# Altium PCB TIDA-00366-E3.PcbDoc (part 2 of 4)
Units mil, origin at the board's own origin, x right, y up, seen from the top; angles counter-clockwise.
Board outline 6298.95 x 6141.73 mil, 4 copper layers (Top Layer, GND, PWR, Bottom Layer), stack 79.834 mil thick; 362 components, 168 nets, 919 pads, 271 vias.
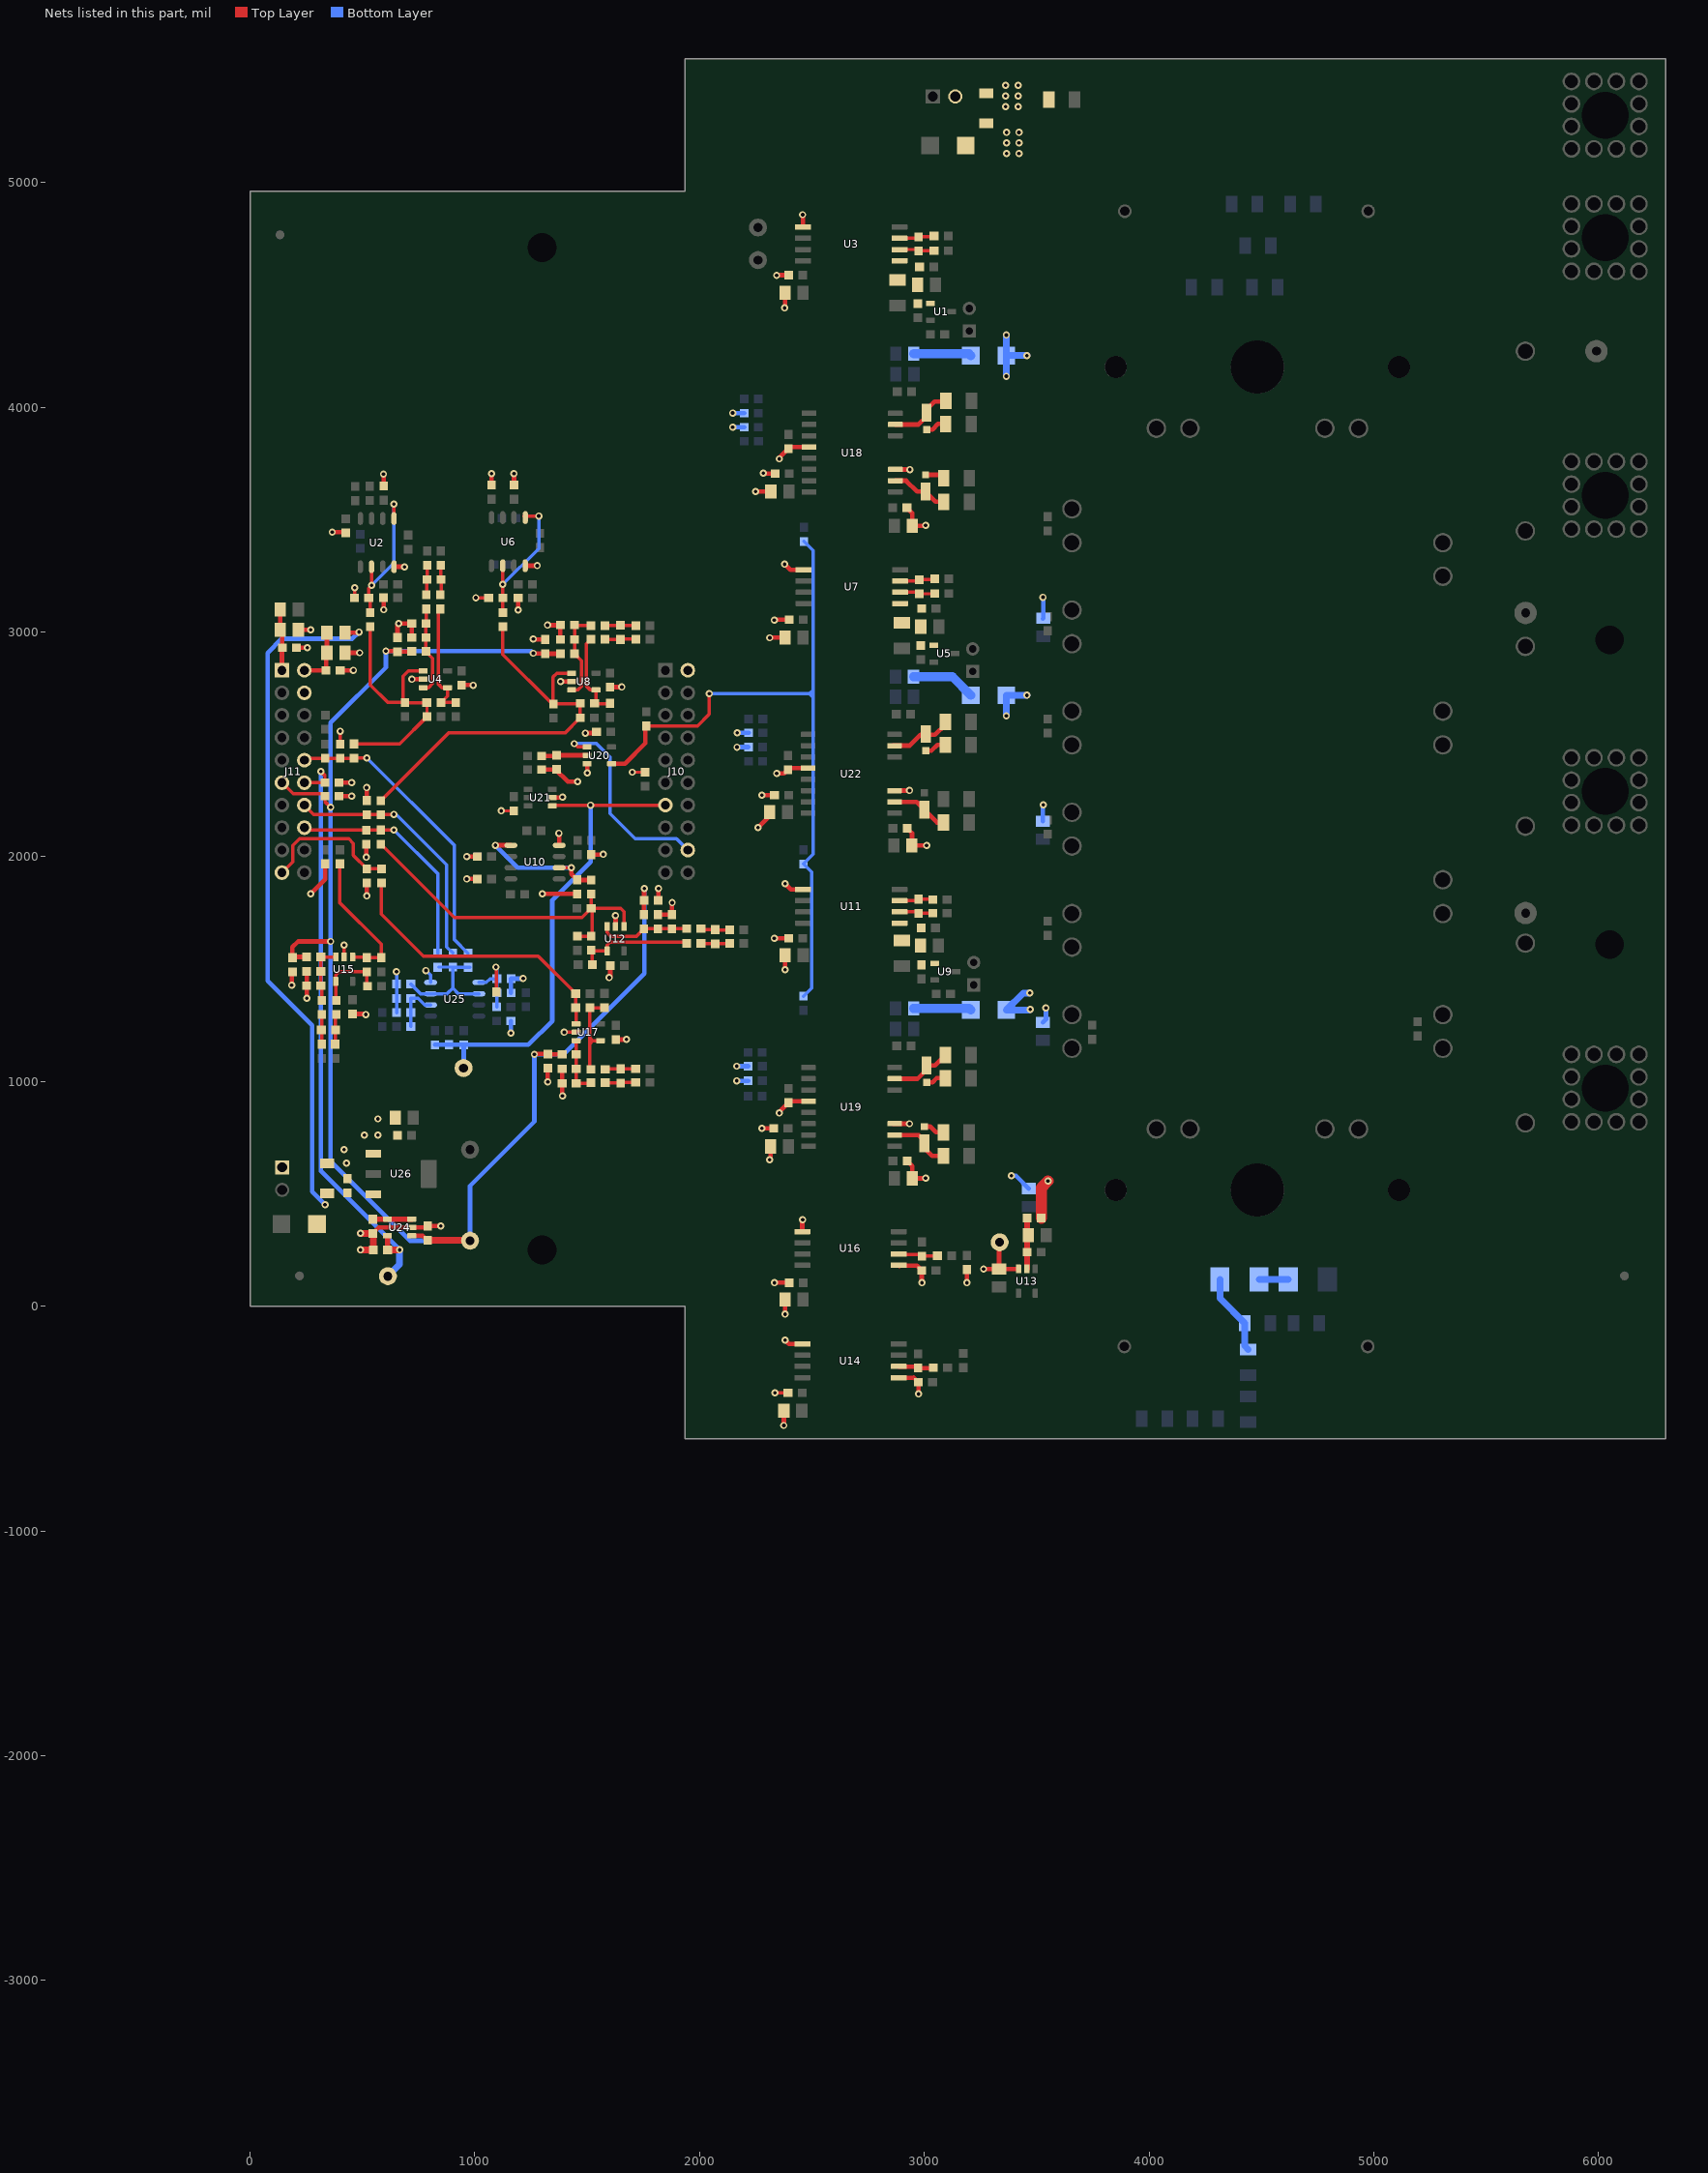
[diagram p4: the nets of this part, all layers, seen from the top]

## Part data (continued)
C3 C11 C13 C17 C25 C27 C31 C39 C41: library part CMP-0007191-4, "CAP, CERM, 180 pF, 50 V, +/- 5%, C0G/NP0, 0603", Cap_Case=0603, Manufacturer=MuRata, Supplier Part Number 1=490-1433-1-ND, TempCo=C0G/NP0, Tolerance_%=5%, Value1=Unknown, Value2=50V, ValueDisplayed=180pF
C4 C6 C18 C20 C32 C34 C43 C45 C48 C59 C69 C70 C72 C73 C79 C81 C83 C84 C87 C92 C94: "CAP, CERM, 4.7 µF, 50 V, +/- 10%, X5R, 0805", Cap_Case=0805, Manufacturer=TDK, Supplier Part Number 1=445-5980-1-ND, TempCo=X5R, Tolerance_%=10, Value1=Unknown, Value2=50V, ValueDisplayed=4.7µF
C5 C7 C9 C14 C19 C21 C23 C28 C33 C35 C37 C42 C44 C47 C49 C50 C53 C56 C58 C60 C61 C64 C66 C74 C75 C76 C77 C78 C80 C85 C86 C93 C97 C98 C104 C105 C109 C110 C111 C112: library part CMP-0007144-4, "CAP, CERM, 0.1 uF, 50 V, +/- 10%, X7R, 0603", Cap_Case=0603, Manufacturer=MuRata, Supplier Part Number 1=490-4779-1-ND, TempCo=X7R, Tolerance_%=10%, Value1="0.02 ohm", Value2=50V, ValueDisplayed=0.1uF
C8 C22 C36: "CAP, CERM, 1500 pF, 100 V, +/- 5%, X7R, 0603", Cap_Case=0603, Manufacturer=AVX, Supplier Part Number 1=478-3703-1-ND, TempCo=X7R, Tolerance_%=5, Value1="0.229 ohm", Value2=100V, ValueDisplayed=1500pF
C10 C12 C24 C26 C38 C40 C46 C51 C52 C54 C57 C62 C63 C65 C71: "CAP, CERM, 0.01 µF, 16 V, +/- 10%, X7R, 0603", Cap_Case=0603, Manufacturer="Wurth Elektronik", Supplier Part Number 1=732-7959-1-ND, TempCo=X7R, Tolerance_%=10, Value1=Unknown, Value2=16V, ValueDisplayed=0.01µF
C67 C68 C82: library part CMP-0007050-4, "CAP, CERM, 0.47 uF, 50 V, +/- 10%, X7R, 0603", Cap_Case=0603, Manufacturer=TDK, Supplier Part Number 1=445-5952-1-ND, TempCo=X7R, Tolerance_%=10%, Value1="0.010974 ohm", Value2=50V, ValueDisplayed=0.47uF
C88 C106: library part CMP-0009015-2, "CAP, CERM, 10 uF, 50 V, +/- 10%, X5R, AEC-Q200 Grade 1, 1206", Cap_Case=1206, Manufacturer=MuRata, Supplier Part Number 1=490-12456-1-ND, TempCo=X5R, Tolerance_%=10%, Value1=Unknown, Value2=50V, ValueDisplayed=10uF
C89 C90: library part CMP-0012358-3, "CAP, Film, 5 uF, 1300 V, +/- 10%, 0.0098 ohm, TH", Cap_Case=31.5x22x36.5mm, Manufacturer=TDK, Supplier Part Number 1=495-3930-ND, Tolerance_%=10%, Value1="0.0098 ohm", Value2=1300V, ValueDisplayed=5uF
C91 C96 C99 C100 C101 C102: library part CMP-0078152-1, "CAP, CERM, 10 pF, 100 V,+/- 5%, C0G/NP0, 0603", Cap_Case=0603, Manufacturer="Wurth Elektronik", Supplier Part Number 1=732-12038-1-ND, TempCo=C0G/NP0, Tolerance_%=5%, Value2=100V, ValueDisplayed=10pF
C95: "CAP, CERM, 0.1 µF, 50 V, +/- 10%, X7R, 0603", Cap_Case=0603, Manufacturer=TDK, Supplier Part Number 1=445-1314-1-ND, TempCo=X7R, Tolerance_%=10, Value1="0.017 ohm", Value2=50V, ValueDisplayed=0.1µF
C103 C107 C113: library part CMP-0006972-5, "CAP, CERM, 820 pF, 50 V, +/- 10%, X7R, 0603", Cap_Case=0603, Manufacturer=Kemet, Supplier Part Number 1=399-1078-1-ND, TempCo=X7R, Tolerance_%=10%, Value1=Unknown, Value2=50V, ValueDisplayed=820pF
C108: library part CMP-0007990-2, "CAP, CERM, 22 uF, 25 V, +/- 20%, X5R, 0805", Cap_Case=0805, Manufacturer="Samsung Electro-Mechanics", Supplier Part Number 1=1276-2908-1-ND, TempCo=X5R, Tolerance_%=20%, Value1=Unknown, Value2=25V, ValueDisplayed=22uF
Caution1: library part IEC_Caution, "IEC 61010-1 Caution Warning"
"CAUTION HOT SURFACE1": library part IEC_HotSurface, "IEC 61010-1 Hot Surface Warning"
D1 D2: "Diode, Zener, 200 V, 550 mW, SMB", Manufacturer="ON Semiconductor", Power_W=0.55, Supplier Part Number 1=863-1SMB5956BT3G, Value1=0.55W
D3 D4 D9: "Diode, Ultrafast, 1300 V, 1 A, SMA", Manufacturer=Vishay-Semiconductor, Supplier Part Number 1=BYG23T-M3/CT-ND, Value1=1A, Value2=1.9V
D5 D6 D7 D8 D10 D11: library part MSS1P3L-M3/89A, "Diode, Schottky, 30 V, 2 A, AEC-Q101, MicroSMP", Manufacturer=Vishay-Semiconductor, Supplier Part Number 1=MSS2P3-M3/89AGICT-ND, Value1=2A, Value2=0.6V
D12 D13: "Diode, Schottky, 100 V, 1 A, SMA", Manufacturer="Diodes Inc.", Supplier Part Number 1=B1100-FDICT-ND, Value1=1A, Value2=0.79V
FID1 FID2 FID3 FID4 FID5 FID6: "Fiducial mark.  There is nothing to buy or mount.", Manufacturer=N/A
H1 H2 H3 H4: library part "MH 3_0.5MM", "Mountin hole, NPTH Drill 3.2mm", Manufacturer=N/A
H5 H6 H7 H8: library part CMP-0003610-1, Manufacturer=Keystone, Supplier Part Number 1=36-1902C-ND
J1 J2 J3: "Header, 100mil, 2x1, TH", Manufacturer=Mill-Max, Supplier Part Number 1=ED7202-ND
J4 J5 J6 J7 J9: "Power Element Bush, M4, 12, TH", Manufacturer="Wurth Elektronik", Supplier Part Number 1=732-3207-ND
J8 J12: "Terminal Block, 2x1, 2.54mm, TH", Manufacturer="TE Connectivity", Supplier Part Number 1=A98333-ND
J10 J11: "Header, 100mil, 10x2, Gold, TH", Color=Black, Current_A=6.3, Manufacturer=Samtec, Supplier Part Number 1=SAM1028-10-ND, Voltage_V=550
LBL1: library part THT-14-423-10, "Thermal Transfer Printable Labels, 0.650\" W x 0.200\" H - 10,000 per roll", Alternate Manufacturer=-, Manufacturer=Brady, Supplier Part Number 1=2065596
LOGO1 LOGO4 LOGO5 LOGO6: library part IEC_HighVoltage, "IEC 61010-1 High Voltage Warning"
Logo2: library part Pb-Free
Logo3: library part FCC_disclaimer, "FCC_disclaimer"
Pb_Free1: library part ESD_Susceptible, "ESD Susceptible Symbol"
R1 R2 R6 R23 R27 R44 R48 R103 R106 R107 R116 R117 R125 R131 R151 R157: library part CMP-0025886-5, "RES, 10 k, 5%, 0.1 W, 0603", Manufacturer=Yageo, Power_W=100mW, Supplier Part Number 1=311-10KGRCT-ND, TempCo="100 ppm/C", Tolerance_%=5%, Value2=0.1W, Value_Code=10k0, ValueDisplayed=10k
R3 R7 R10 R14 R17 R20 R24 R28 R31 R35 R38 R41 R45 R49 R52 R56 R59 R62 R67 R71 R87 R102 R110 R111 R127: library part CMP-0025885-5, "RES, 0, 5%, 0.1 W, 0603", Manufacturer=Yageo, Power_W=100mW, Supplier Part Number 1=311-0.0GRCT-ND, TempCo="200 ppm/C", Tolerance_%=5%, Value2=0.1W, Value_Code=0000, ValueDisplayed=0
R4 R19 R25 R40 R46 R61: "RES, 100, 0.1%, 0.1 W, AEC-Q200 Grade 0, 0603", Manufacturer=Panasonic, Power_W=0.1, Supplier Part Number 1=P100DBCT-ND, TempCo="25 ppm/C", Value1=0.1%, Value2=0.1W, Value_Code=100R, ValueDisplayed=100
R5 R26 R47 R78 R92 R143 R145 R150 R152 R153 R156: library part CMP-0022736-4, "RES, 100, 1%, 0.1 W, 0603", Manufacturer=Yageo, Power_W=100mW, Supplier Part Number 1=311-100HRCT-ND, TempCo="100 ppm/C", Tolerance_%=1%, Value2=0.1W, Value_Code=100R, ValueDisplayed=100
R8 R21 R22 R29 R42 R43 R50 R63 R64 R86 R99: "RES, 7.50 k, 1%, 0.1 W, 0603", Manufacturer=Panasonic, Power_W=0.1, Supplier Part Number 1=P7.50KHCT-ND, TempCo="100 ppm/C", Tolerance_%=1, Value1=1%, Value2=0.1W, Value_Code=7k50, ValueDisplayed=7.50k
R9 R30 R51: library part CMP-0018732-3, "RES, 820, 5%, 0.25 W, AEC-Q200 Grade 0, 1206", Manufacturer=Vishay-Dale, Power_W=250mW, Supplier Part Number 1=541-820ECT-ND, TempCo="200 ppm/C", Tolerance_%=5%, Value2=0.25W, Value_Code=820R, ValueDisplayed=820
R11 R32 R53: "RES, 10.7 k, 0.1%, 0.1 W, 0603", Manufacturer="Susumu Co Ltd", Power_W=0.1, Supplier Part Number 1=RG16P10.7KBCT-ND, TempCo="25 ppm/C", Value1=0.1%, Value2=0.1W, Value_Code=10k7, ValueDisplayed=10.7k
R12 R13 R15 R16 R33 R34 R36 R37 R54 R55 R57 R58 R75 R76 R80 R81 R90 R91 R93 R94: "RES, 4.70 k, 1%, 0.1 W, 0603", Manufacturer="Yageo America", Power_W=0.1, Supplier Part Number 1=311-4.70KHRCT-ND, TempCo="200 ppm/C", Tolerance_%=1, Value1=1%, Value2=0.1W, Value_Code=4k70, ValueDisplayed=4.70k
R18 R39 R60 R77 R148 R149: "RES, 0, 5%, 0.1 W, 0603", Manufacturer=Vishay-Dale, Power_W=0.1, Supplier Part Number 1=541-0.0GCT-ND, TempCo="200 ppm/C", Tolerance_%=5, Value1=5%, Value2=0.1W, Value_Code=0000, ValueDisplayed=0
R65 R66 R69 R70 R73: library part CMP-0018060-2, "RES, 200 k, 1%, 0.25 W, 1206", Manufacturer="Yageo America", Power_W=250mW, Supplier Part Number 1=311-200KFRCT-ND, TempCo="100 ppm/C", Tolerance_%=1%, Value2=0.25W, Value_Code=200k
R68: library part CMP-0018756-2, "RES, 0, 5%, 0.25 W, 1206", Manufacturer=Rohm, Power_W=250mW, Supplier Part Number 1=RHM0.0ECT-ND, TempCo="200 ppm/C", Tolerance_%=5%, Value2=0.25W, Value_Code=0000, ValueDisplayed=0
R72 R85 R88 R98: library part CMP-0022816-5, "RES, 15.0 k, 1%, 0.1 W, 0603", Manufacturer=Yageo, Power_W=100mW, Supplier Part Number 1=311-15.0KHRCT-ND, TempCo="100 ppm/C", Tolerance_%=1%, Value2=0.1W, Value_Code=15k0, ValueDisplayed=15.0k
R74 R89: "RES, 39, 5%, 0.1 W, 0603", Manufacturer=Vishay-Dale, Power_W=0.1, Supplier Part Number 1=541-39GCT-ND, TempCo="200 ppm/C", Tolerance_%=5, Value1=5%, Value2=0.1W, Value_Code=39R0, ValueDisplayed=39
R79: library part CMP-0022990-5, "RES, 2.49 k, 1%, 0.1 W, 0603", Manufacturer=Yageo, Power_W=100mW, Supplier Part Number 1=311-2.49KHRCT-ND, TempCo="100 ppm/C", Tolerance_%=1%, Value2=0.1W, Value_Code=2k49, ValueDisplayed=2.49k
R100 R101 R120: library part CMP-0021875-2, "RES, 1.33, 1%, 0.125 W, 0805", Manufacturer="Yageo America", Power_W=125mW, Supplier Part Number 1=311-1.33CRCT-ND, TempCo="200 ppm/C", Tolerance_%=1%, Value2=0.125W, Value_Code=1R33, ValueDisplayed=1.33
R104 R105 R114 R115 R122 R130 R141: library part CMP-0018748-1, "RES, 0, 5%, 0.25 W, 1206", Manufacturer=Panasonic, Power_W=250mW, Supplier Part Number 1=P0.0ECT-ND, TempCo="600 ppm/C", Tolerance_%=5%, Value2=0.25W, Value_Code=0000, ValueDisplayed=0
R108 R109 R118 R119 R126 R132: "RES, 16.5, 1%, 0.25 W, 1206", Manufacturer=Vishay-Dale, Power_W=0.25, Supplier Part Number 1=541-16.5FCT-ND, TempCo="100 ppm/C", Tolerance_%=1, Value1=1%, Value2=0.25W, Value_Code=16R5, ValueDisplayed=16.5
R112 R113 R128: library part CMP-0022906-5, "RES, 20.0 k, 1%, 0.1 W, 0603", Manufacturer=Yageo, Power_W=100mW, Supplier Part Number 1=311-20.0KHRCT-ND, TempCo="100 ppm/C", Tolerance_%=1%, Value2=0.1W, Value_Code=20k0, ValueDisplayed=20.0k
R121 R123 R124: "RES, 0.005, 1%, 5 W, 20.32x4.80mm", Manufacturer=Bourns, Power_W=5, Supplier Part Number 1=PWR4412-2SDR0050F-ND, TempCo="20 ppm/C", Tolerance_%=1, Value1=1%, Value2=5W, Value_Code=5L000, ValueDisplayed=0.005
R129: library part CMP-0022692-3, "RES, 22.0 k, 1%, 0.1 W, AEC-Q200 Grade 0, 0603", Manufacturer=Panasonic, Power_W=100mW, Supplier Part Number 1=P22.0KHCT-ND, TempCo="100 ppm/C", Tolerance_%=1%, Value2=0.1W, Value_Code=22k0, ValueDisplayed=22.0k
R133 R139 R140 R142 R144 R146: "RES, 0, 5%, 0.125 W, 0805", Manufacturer=Vishay-Dale, Power_W=0.125, Supplier Part Number 1=541-0.0ACT-ND, TempCo="200 ppm/C", Tolerance_%=5, Value1=5%, Value2=0.125W, Value_Code=0000, ValueDisplayed=0
R134 R135 R136 R137 R138: "RES, 100 k, 5%, 0.25 W, 1206", Manufacturer=Vishay-Dale, Power_W=0.25, Supplier Part Number 1=541-100KECT-ND, TempCo="200 ppm/C", Tolerance_%=5, Value1=5%, Value2=0.25W, Value_Code=100k
R147: "RES, 1.0 k, 5%, 0.1 W, 0603", Manufacturer="Yageo America", Power_W=0.1, Supplier Part Number 1=311-1.0KGRCT-ND, TempCo="100 ppm/C", Tolerance_%=5, Value1=5%, Value2=0.1W, Value_Code=1k00, ValueDisplayed=1.0k
R154: "RES, 200, 0.1%, 0.1 W, 0603", Manufacturer="Susumu Co Ltd", Power_W=0.1, Supplier Part Number 1=RG16P200BCT-ND, TempCo="25 ppm/C", Value1=0.1%, Value2=0.1W, Value_Code=200R, ValueDisplayed=200
R155: "RES, 12.0 k, 0.1%, 0.1 W, 0603", Manufacturer="Susumu Co Ltd", Power_W=0.1, Supplier Part Number 1=RG16P12.0KBCT-ND, TempCo="25 ppm/C", Value1=0.1%, Value2=0.1W, Value_Code=12k0, ValueDisplayed=12.0k
R158 R160 R161 R162 R166: "RES, 10.0 k, 0.1%, 0.0375 W, 0603", Manufacturer="Vishay Sfernice", Power_W=0.0375, Supplier Part Number 1=PHTB-10KCT-ND, TempCo="15 ppm/C", Tolerance_%=0.1, Value1=0.1%, Value2=0.0375W, Value_Code=10k0, ValueDisplayed=10.0k
R159 R164: "RES, 0, 5%, 0.1 W, 0603", Manufacturer="Yageo America", Power_W=0.1, Supplier Part Number 1=311-0.0GRCT-ND, TempCo="200 ppm/C", Tolerance_%=5, Value1=5%, Value2=0.1W, Value_Code=0000, ValueDisplayed=0
R163: "RES, 0, 5%, 0.1 W, 0603", Manufacturer=Panasonic, Power_W=0.1, Supplier Part Number 1=P0.0GCT-ND, TempCo="600 ppm/C", Tolerance_%=5, Value1=5%, Value2=0.1W, Value_Code=0000, ValueDisplayed=0
R165: "RES, 8.20 k, 0.1%, 0.1 W, 0603", Manufacturer="Susumu Co Ltd", Power_W=0.1, Supplier Part Number 1=RG16P8.2KBCT-ND, TempCo="25 ppm/C", Value1=0.1%, Value2=0.1W, Value_Code=8k20, ValueDisplayed=8.20k
R167: "RES, 5.11 M, 1%, 0.1 W, 0603", Manufacturer=Vishay-Dale, Power_W=0.1, Supplier Part Number 1=541-5.11MHCT-ND, TempCo="100 ppm/C", Tolerance_%=1, Value1=1%, Value2=0.1W, Value_Code=5M11, ValueDisplayed=5.11M
TP1 TP2 TP3 TP7 TP8 TP9 TP10: "Test Point, Miniature, Red, TH", Color=Red, Manufacturer=Keystone, Supplier Part Number 1=36-5000-ND
TP4 TP5 TP6: library part PAD_100mil-40milhole, "100mil pad, 40mil hole", Manufacturer=Any
U1 U5 U9: "Adjustable Precision Shunt Regulator, 34 ppm / degC, 100 mA, -40 to 125 degC, 3-pin SOT-23 (DBZ), Green (RoHS & no Sb/Br)", Alternate Manufacturer="Texas Instruments", Alternate PartNumber=Equivalent, Rating=Catalog, Supplier Part Number 1=296-26715-2-ND, Temp Coeff(Max)(ppm/ degree C)=92, Temp Coeff(Typ)(ppm/ degree C)=34
U2 U6 U10 U25: "LinCMOS Dual Differential Comparators, D0008A", Alternate Manufacturer="Texas Instruments", Alternate PartNumber=TLC372QD
U3 U7 U11: "200 kHz, Fully-Differential Isolation Amplifier, DWV0008A", Alternate Manufacturer="Texas Instruments", Alternate PartNumber=AMC1301DWV
U4 U8 U12 U15 U17: "Precision, 20 MHz, 0.9 pA Ib, RRIO, CMOS Operational Amplifier, 1.8 to 5.5 V, -40 to 125 degC, 5-pin SOT23 (DBV0005A), Green (RoHS & no Sb/Br)", Alternate Manufacturer="Texas Instruments", Alternate PartNumber=Equivalent, Supplier Part Number 1=296-29480-2-ND, Total Supply Voltage(Max)(+5V is 5, +/-5V is 10)=5.5, Total Supply Voltage(Min)(+5V is 5, +/-5V is 10)=1.8
U13: library part CMP-0035558-1, "Single Output LDO, 150 mA, Fixed 5 V Output, 2.5 to 24 V Input, with Ultra-Low IQ, 5-pin SOT-23 (DBV), -40 to 125 degC, Green (RoHS & no Sb/Br)", Manufacturer="Texas Instruments"
U14 U16: library part CMP-0013503-1, "Precision, 2-V Input, Reinforced Isolated Amplifier, DWV0008A (SOIC-8)", Alternate Manufacturer="Texas Instruments", Alternate PartNumber=AMC1311DWV
U18 U19 U22: library part CMP-0083996-1, "4-A, 6-A, 5.7-kVRMS Isolated Dual-Channel Gate Driver with Enable, DWK0014A (SOIC-14)", Alternate Manufacturer="Texas Instruments", Alternate PartNumber=UCC21530DWKR
U20: library part CMP-0051622-1, "Single 2-Input Positive-OR Gate, DBV0005A, LARGE T&R", F @ Nom Voltage(Max)(Mhz)=150, Generic Part Number=SN74LVC1G32, ICC @ Nom Voltage(Max)(mA)=0.01, Manufacturer="Texas Instruments", Operating Temperature Range(C)="-40 to 125,-40 to 85", Rating=Catalog, tpd @ Nom Voltage(Max)(ns)=7.2,4.4,3.6,3.4, Voltage(Nom)(V)=1.8,2.5,3.3,5
U21: library part CMP-0051219-1, "Single 3-Input Positive-AND Gate, DBV0006A, LARGE T&R", F @ Nom Voltage(Max)(Mhz)=150, Generic Part Number=SN74LVC1G11, ICC @ Nom Voltage(Max)(mA)=0.01, Manufacturer="Texas Instruments", Operating Temperature Range(C)="-40 to 125,-40 to 85", Rating=Catalog, tpd @ Nom Voltage(Max)(ns)=20,7.8,6.2,4.6, Voltage(Nom)(V)=1.8,2.5,3.3,5
U23: library part "MWI 50-12T7T", "IGBT MOD 1200V 85A E2-Pack", Manufacturer=IXYS, Supplier Part Number 1=747-MIXA60W1200TED
U24: "Low-Drift, Low-Power, Dual-Output, VREF and VREF / 2 Voltage References, DDC0005A", Alternate Manufacturer="Texas Instruments", Alternate PartNumber=REF2033AIDDCT
U26: "FIXED LOW-DROPOUT VOLTAGE REGULATOR, DCY0003A", Alternate Manufacturer="Texas Instruments"
ZZ1: library part AssemblyNoteLabel, Alternate Manufacturer=-
ZZ2 ZZ3 ZZ4: library part AssemblyNote, Alternate Manufacturer=-

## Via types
v1: diameter 32, hole 16, Top Layer to Bottom Layer, 271 vias

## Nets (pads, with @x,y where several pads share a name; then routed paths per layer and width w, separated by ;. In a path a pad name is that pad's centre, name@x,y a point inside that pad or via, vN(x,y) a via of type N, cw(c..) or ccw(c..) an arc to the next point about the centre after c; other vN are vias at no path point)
1V65_REF: C14.2 C28.2 C42.2 C56.2 C66.2 C97.1 C112.1 J11.11 R22.1 R43.1 R64.1 R86.1 R99.1 TP8.1 U24.1 | length 7075.5
  Top Layer w15: J11.11@141.73,2329.45 191.73,2279.45 323.24,2279.45 C97.1@333.24,2269.45 333.24,2244.95 v1(358.73,2219.45) ; C112.1@786.92,294.11 C112.1@790.38,294.11
  Top Layer w20: C56.2@188.73,1550.9 188.73,1597.91 213.73,1622.91 v1(358.73,1622.91) ; C56.2@192.23,1554.4 R86.1@252.23,1554.4 ; v1(604.23,2914.95) 654.73,2914.95 656.24,2913.45 R22.1@719.24,2913.45 ; U24.1@719.51,313.21 767.83,313.21 C112.1@786.92,294.11 ; v1(1260.07,2905.12) 1261.57,2903.63 C14.2@1313.06,2903.63 1313.57,2903.12 R43.1@1380.57,2903.12 ; v1(1264.73,1120.91) 1266.23,1122.4 C66.2@1324.73,1122.4 1326.23,1120.91 R99.1@1388.24,1120.91 ; R64.1@1752.41,1742.4 1752.41,1805.4 C42.2@1752.92,1805.91 1752.92,1857.4 v1(1754.41,1858.9)
  Top Layer w30: C112.1@790.38,294.11 976.07,294.11 TP8.1@978.73,291.45
  Bottom Layer w20: v1(1260.07,2905.12) 1250.24,2914.95 v1(604.23,2914.95) 604.23,2842.23 358.73,2596.73 v1(358.73,2219.45) v1(358.73,1622.91) 358.73,644.27 711.55,291.45 TP8.1@978.73,291.45 978.73,535.73 1264.73,821.73 v1(1264.73,1120.91) 1395.87,1120.91 1754.41,1479.45 v1(1754.41,1858.9)
3V3_REF: C98.1 C111.1 J11.12 TP7.1 U24.5 | length 2679.6
  Top Layer w15: J11.12@241.73,2329.45 C98.1@333.24,2329.45 333.24,2360.95 v1(314.73,2379.45)
  Top Layer w20: C111.1@611.24,251.24 C111.1@611.87,250.61
  Top Layer w23.62: C111.1@611.24,251.24 U24.5@611.24,313.21
  Top Layer w30: C111.1@611.87,250.61 v1(665.38,250.61)
  Bottom Layer w20: v1@315.73,2378.45 v1(314.73,2379.45) 314.73,601.25 v1(665.38,250.61)
  Bottom Layer w30: TP7.1@613.38,133.61 665.38,185.61 v1(665.38,250.61)
5V0: C104.1 C105.1 C106.1 D13.1 R144.2 U24.3 U24.4 U26.3 | length 3244.3
  Top Layer w20: R144.2@421.73,2996.45 481.73,2996.45 v1(484.73,2999.45)
  Top Layer w23.62: C105.1@546.38,387.1 547.28,388.01 U24.4@611.24,388.01 U24.3@719.51,388.01
  Bottom Layer w20: v1(333.73,451.45) 276,509.18 276,1249 78,1447 78,2907 141,2970 455.28,2970 v1(484.73,2999.45)
5V_VDC: C45.1 C47.2 C58.2 R129.1 TP3.1 U13.3 U14.1 U16.1 | length 647.2
  Top Layer w20: U14.1@2886.13,-318 2952.14,-318 2952.42,-317.73 C47.2@2973.24,-338.55 2973.73,-339.05 v1(2973.73,-390.55) ; U16.1@2889.3,179.45 2890.12,180.27 2967.42,180.27 C58.2@2988.24,159.45 2988.24,105.95 v1(2989.73,104.45) ; v1(3189.73,104.45) R129.1@3189.73,162.95 ; v1(3263.33,165.32) C45.1@3332.33,165.32 ; TP3.1@3334.73,284.45 3332.33,282.05 C45.1@3332.33,165.32 ; U13.3@3419.93,164.45 3418.6,164.45 3417.73,165.32 C45.1@3332.33,165.32
+16V_GPS: C72.2 C73.2 C75.2 C76.2 C84.2 C85.2 C88.1 D3.2 D4.2 D9.2 D12.1 R67.1 U18.11 U19.11 U22.11 | length 1542.3
  Top Layer w20: U19.11@2860.12,811.86 v1(2934.13,811.86) ; U18.11@2861,3722.45 v1(2935,3722.45) ; U22.11@2866.86,2294 2933.55,2294 v1(2934,2294.45) ; C75.2@2922.23,3552.45 2945.73,3528.95 C72.2@2945.73,3472.45 3003.73,3472.45 v1(3005.73,3474.45) ; C85.2@2923.23,2126.45 2944.73,2104.95 C84.2@2944.73,2049.45 v1(3009.73,2049.45) ; C76.2@2923.36,645.86 2945.86,623.36 C73.2@2945.86,568.86 3004.15,568.86 v1(3005.73,570.45)
  Top Layer w50: R67.1@3519.83,392.32 3519.83,527.54 v1(3549.73,557.45)
  Bottom Layer w30: v1(3364.47,2626.71) D9.2@3364.47,2718.45 v1(3456.21,2718.45) ; v1(3364.47,4137.71) D3.2@3364.47,4229.45 ; v1(3364.47,4321.19) D3.2@3364.47,4229.45 ; v1(3456.21,4229.45) D3.2@3364.47,4229.45 ; v1(3468.73,1393.45) 3439.47,1393.45 D4.2@3364.47,1318.45 3468.73,1318.45 v1(3470.73,1320.45)
  other v1: 3365.73,5128.45 3420.73,5128.45 3365.73,5175.45 3420.73,5175.45 3365.73,5222.45 3420.73,5222.45
ENABLE: R110.1 R111.1 R127.1 R147.1 U20.4 | length 3250.9
  Top Layer w15: R147.1@1759,2578.5 R147.1@1760.05,2577.45 ; R147.1@1763,2581.5 1827.83,2581.5 ; 1827.86,2581.47 1990.47,2581.47 2043.28,2634.28 v1(2043.28,2725)
  Top Layer w20: U20.4@1608.13,2413.6 1667.6,2413.6 1759,2505 R147.1@1759,2578.5
  Bottom Layer w15: v1(2043.28,2725) 2505,2725 ; R111.1@2462,1379.5 2498,1415.5 2498,1931.5 R127.1@2462,1967.5 2505,2010.5 2505,2725 ; R110.1@2464.73,3402.5 2505,3362.24 2505,2725 ; 2505,2709 2489,2725 2505,2741
GND: C1.2 C2.2 C6.1 C7.1 C8.2 C9.1 C12.2 C13.2 C14.1 C15.2 C16.2 C20.1 C21.1 C22.2 C23.1 C26.2 C27.2 C28.1 C29.2 C30.2 C34.1 C35.1 C36.2 C37.1 C40.2 C41.2 C42.1 C48.1 C49.1 C50.1 C53.2 C54.2 C56.1 C59.1 C60.1 C61.1 C64.2 C65.2 C66.1 C71.2 C74.2 C77.2 C78.2 C79.2 C80.2 C81.2 C86.2 C87.2 C91.2 C92.1 C93.1 C94.2 C95.2 C96.2 C97.2 C98.2 C99.2 C100.2 C101.2 C102.2 C103.2 C104.2 C105.2 C106.2 C107.2 C108.2 C109.2 C110.2 C111.2 C112.2 C113.2 J10.2 J11.4 J12.1 R19.1 R21.1 R40.1 R42.1 R61.1 R63.1 R85.1 R98.1 R103.1 R112.1 R113.1 R128.1 R151.1 R158.2 R166.2 U2.4 U3.5 U4.2 U6.4 U7.5 U8.2 U10.4 U11.5 U12.2 U14.5 U15.2 U16.5 U17.2 U18.4 U19.4 U20.3 U21.2 U22.4 U24.2 U25.4 U26.1 | length 6567.5
  Top Layer w12: v1(1117.08,2204.24) C77.2@1173.57,2204.24 C77.2@1174.33,2203.48
  Top Layer w15: C8.2@400.73,2500.95 v1(400.73,2558.45) ; U15.2@418.73,1553.54 v1(418.73,1606.4) ; C12.2@465.25,3150.95 466.76,3152.46 465.25,3153.97 v1(465.25,3197) ; v1(1004.5,3152.19) C26.2@1061.32,3152.19 ; v1(1397.73,1218.91) U17.2@1450.6,1218.91 ; v1(1700.23,2375.95) R151.1@1757.73,2375.95 ; v1(2334.73,-385.55) C49.1@2393.24,-385.55
  Top Layer w20: C56.1@181.72,1487.91 185.23,1484.4 v1(185.23,1427.91) ; C93.1@206.23,2929.45 v1(254.73,2929.45) ; C92.1@214.73,3009.45 v1(269.73,3009.45) ; v1(252.23,1369.91) C54.2@252.23,1426.4 R85.1@252.23,1489.4 ; v1(269.73,1834.45) 334.73,1899.45 C53.2@334.73,1967.95 ; v1(365.51,3444.35) C1.2@422.01,3444.35 ; C97.2@396.23,2269.45 v1(451.73,2269.45) ; C98.2@396.23,2329.45 v1(451.73,2329.45) ; C95.2@401.23,2829.45 v1(459.73,2829.45) ; C94.2@421.73,2907.45 v1(487.73,2907.45) ; C50.1@456.13,1300.5 512.63,1300.5 v1(515.23,1297.91) ; v1(517.73,1997.45) C36.2@517.73,2054.95 ; C22.2@518.73,2249.95 v1(518.73,2307.45) ; v1(519.73,1825.45) C64.2@519.73,1882.95 ; C105.2@548.88,321.61 C105.2@546.38,324.11 571.69,349.42 572.54,349.42 573.72,350.61 U24.2@719.51,350.61 783.88,350.61 C112.2@790.38,357.1 v1(848.87,357.1) ; v1(593.66,3702.34) 594.09,3701.91 R19.1@594.09,3648.91 ; C2.2@594.02,3152.34 594.02,3099.34 v1(594.44,3098.91) ; U2.4@640.51,3290.06 687.13,3290.06 v1(687.73,3289.45) ; C28.1@655.73,2974.95 655.73,3031.45 v1(661.73,3037.45) C13.2@719.24,3037.45 R21.1@719.24,2975.45 ; v1(720.1,2789.45) U4.2@770.6,2789.45 ; C9.1@940.83,2763.86 991.33,2763.86 v1(992.24,2762.95) ; v1(963.92,1900.91) C29.2@1011.39,1900.91 ; v1(963.92,2000.91) R61.1@1011.39,2000.91 ; v1@1073.79,3706.68 1074.21,3706.25 C15.2@1074.21,3653.25 ; v1@1173.79,3706.68 1174.21,3706.25 R40.1@1174.21,3653.25 ; C16.2@1192.72,3151.76 1192.72,3098.76 v1(1193.14,3098.33) ; U6.4@1224.21,3294.47 1277.21,3294.47 v1(1277.64,3294.9) ; v1(1260.07,2968.11) 1261.57,2966.62 C14.1@1313.06,2966.62 C14.1@1313.57,2966.11 ; R103.1@1297.23,2388.23 1359.24,2388.23 1413.46,2334 v1(1457,2334) ; v1(1299.73,1834.45) v1(1299.73,1834.45) C40.2@1454.96,1834.41 ; v1(1323.06,3030.12) C27.2@1380.54,3030.12 ; v1(1324.73,997.91) 1323.24,999.41 1323.24,1057.91 C66.1@1324.73,1059.41 ; U21.2@1345.13,2263 1388,2263 v1(1390,2265) ; v1(1374.14,2104.46) 1375.17,2103.44 U10.4@1375.17,2050.91 ; R42.1@1380.57,2966.12 1380.57,3030.14 C27.2@1381.04,3030.62 ; v1(1381.43,2779.12) U8.2@1430.93,2779.12 U8.2@1431.93,2779.12 ; R98.1@1388.24,1055.91 C65.2@1388.24,990.91 1388.24,937.4 v1(1389.73,935.91) ; v1(1492,2550) 1536.5,2550 C74.2@1541.5,2555 ; v1(1499.87,2372.13) U20.3@1499.87,2413.6 ; C30.2@1517.88,2009.41 1570.41,2009.41 v1(1571.44,2010.43) ; v1(1597.96,1461.91) 1602.5,1466.45 C37.1@1602.5,1515 ; C23.1@1602,2754.5 1653.45,2754.5 v1(1653.76,2754.82) ; U12.2@1625.96,1688.04 U12.2@1625.96,1689.04 v1(1625.96,1738.54) ; C61.1@1627,1186.46 1673.28,1186.46 v1(1674.73,1187.91) ; R63.1@1814.41,1742.4 C41.2@1876.41,1742.4 1876.41,1793.9 v1(1877.91,1795.39) ; C42.1@1815.4,1805.4 C42.1@1815.91,1805.91 1815.91,1857.4 v1(1817.4,1858.9) ; v1(2249.49,3624.95) 2249.99,3625.45 C79.2@2316.99,3625.45 C79.2@2319.99,3622.45 ; v1(2260,2130) 2311.73,2181.73 C87.2@2311.73,2198.45 ; v1(2277.24,2273.95) 2277.74,2273.45 R128.1@2333.24,2273.45 ; v1(2277.37,791.37) 2277.87,790.86 R113.1@2330.37,790.86 R113.1@2333.37,790.86 ; v1(2283.73,3706.45) 2285.73,3704.45 R112.1@2336.24,3704.45 ; v1(2311.86,651.86) 2316,656 C81.2@2316,711 ; v1(2312.23,2973.95) 2312.73,2974.45 C20.1@2379.73,2974.45 C20.1@2382.73,2971.45 ; v1(2332.24,1637.45) C35.1@2396.24,1637.45 ; v1(2332.24,3052.71) 2333.98,3054.45 C21.1@2398.24,3054.45 C21.1@2395.24,3051.45 ; v1(2333.24,104.45) C60.1@2398.24,104.45 C60.1@2399.73,102.95 ; v1(2342.73,4586.45) 2343.73,4587.45 C7.1@2396.24,4587.45 ; v1(2342.98,2370.92) 2376.7,2370.92 C86.2@2392.73,2386.95 ; v1(2354.13,859.41) 2354.13,864.38 C80.2@2395.12,905.37 2401.61,911.86 U19.4@2486.11,911.86 ; v1(2355,3770) 2355,3774.97 C78.2@2395.99,3815.95 2402.49,3822.45 U18.4@2486.98,3822.45 ; v1(2374.73,-530.55) C48.1@2374.73,-465.55 ; v1(2377.73,4441.45) 2379.73,4443.45 C6.1@2379.73,4509.45 ; v1(2378.73,3301.45) 2403.86,3276.32 U7.5@2462.51,3276.32 ; v1(2379.73,-150.55) 2397.18,-168 U14.5@2457,-168 ; v1(2379.73,-35.55) C59.1@2379.73,29.45 C59.1@2381.23,30.95 ; v1(2380.73,1497.45) C34.1@2380.73,1561.45 ; v1(2380.73,1880.45) 2406.73,1854.45 U11.5@2460.17,1854.45 ; C86.2@2400.23,2394.45 U22.4@2483,2394.45 ; U16.5@2457,332 2457,382.78 v1(2458.67,384.45) ; v1(2458.67,4856.58) 2460.17,4855.08 U3.5@2460.17,4801.58
  Top Layer w30: v1(490.87,324.11) C105.2@546.38,324.11 ; v1(491.38,250.61) C111.2@548.88,250.61 C105.2@548.88,321.61
  Bottom Layer w15: v1(651.26,1487.95) 652.26,1486.95 C107.2@652.26,1433.45 C103.2@652.26,1369.45 R158.2@652.26,1306.45 ; v1(782.76,1493.45) 803.47,1472.73 U25.4@803.47,1440.45
  Bottom Layer w20: C110.2@1160.23,1268.99 1160.23,1215.97 v1(1160.75,1215.45) ; R166.2@1161.23,1393.99 C113.2@1161.23,1456.99 1214.21,1456.99 v1(1215.19,1457.97) ; v1(2147.19,3910.99) C96.2@2198.24,3910.99 ; v1(2147.19,3973.99) C91.2@2198.24,3973.99 ; v1(2165.19,1002.99) C102.2@2216.24,1002.99 ; v1(2165.19,1067.99) C101.2@2216.24,1067.99 ; v1(2166.19,2487.65) C100.2@2217.24,2487.65 ; v1(2167.19,2550.99) C99.2@2218.24,2550.99
  other v1: 428.73,636.45 418.73,696.45 508.73,761.45 568.73,761.45 568.73,833.45 1074.15,3704.65 1174.15,3704.65
GND1: C88.2 J8.2 R133.2 R139.2 R140.2 R141.1 R142.2 | length 345.9
  Bottom Layer w20: v1@3383.73,576.45 v1(3387.73,580.45) 3407.73,580.45 R142.2@3464.73,523.45 ; R140.2@3527.73,1262.45 3540.73,1275.45 v1(3540.73,1327.45) ; R139.2@3527.73,2157.45 3527.73,2229.45 v1(3528.73,2230.45) ; R133.2@3527.73,3059.45 R133.2@3528.73,3060.45 3528.73,3153.45 v1(3527.73,3154.45)
  other v1: 3361.73,5337.45 3416.73,5337.45 3361.73,5384.45 3416.73,5384.45 3361.73,5431.45 3416.73,5431.45
GND_FAULT: J10.13 R157.1 R159.2 R164.2 TP10.1 U21.1 | length 2197.2
  Top Layer w15: U21.1@1344.13,2227.6 1512.88,2227.6 v1(1514.73,2229.45) J10.13@1847.73,2229.45
  Bottom Layer w20: R157.1@822.76,1162.95 823.31,1163.5 R159.2@885,1163.5 ; R159.2@885,1163.45 942.26,1163.45 R164.2@942.76,1162.95 ; TP10.1@949.73,1059.45 950.73,1060.45 R164.2@950.73,1162.95 1238.24,1162.95 1344.73,1269.45 1344.73,1806.4 1514.73,1976.4 v1(1514.73,2229.45)
I_U: C8.1 J11.10 R5.2 R148.2 R160.1 | length 1337
  Top Layer w15: J11.10@241.73,2429.45 250.24,2437.95 R148.2@334.73,2437.95 C8.1@400.73,2437.95 461.73,2437.95 R5.2@462.73,2438.95 463.23,2439.45 v1(519.73,2439.45)
  Bottom Layer w15: v1(519.73,2439.45) 909.73,2049.45 909.73,1630.95 R160.1@969.73,1570.95
I_V: C22.1 J11.14 R26.2 R161.1 | length 1153.3
  Top Layer w15: J11.14@241.73,2229.45 283.23,2187.95 507.74,2187.95 C22.1@518.73,2176.95 ; C22.1@518.73,2186.95 R26.2@580.73,2186.95 ; R26.2@581.73,2185.95 R26.2@580.73,2186.95 ; v1(639.73,2188.46) 582.24,2188.46 R26.2@580.73,2186.95
  Bottom Layer w15: v1(639.73,2188.46) 650.73,2188.46 874.73,1964.45 874.73,1598.97 R161.1@901.76,1571.95
I_W: C36.1 J11.16 R47.2 R162.1 | length 1032.7
  Top Layer w15: J11.16@241.73,2129.45 253.24,2117.95 C36.1@517.73,2117.95 580.73,2117.95 R47.2@581.73,2118.95 582.24,2119.45 v1(639.73,2119.45)
  Bottom Layer w15: v1(639.73,2119.45) 834.73,1924.45 R162.1@834.73,1570.95
MCUCntrl: J10.18 U20.1 | length 913.3
  Top Layer w15: v1(1442,2503) 1456.6,2488.4 U20.1@1499.87,2488.4
  Bottom Layer w15: v1(1442,2503) 1541.84,2503 1601,2443.84 1601,2192 1713,2080 1897.18,2080 J10.18@1947.73,2029.45
MODULE_TEMP: C64.1 J11.19 R92.2 | length 633.9
  Top Layer w15: J11.19@141.73,1929.45 189.73,1977.45 189.73,2049.45 219.73,2079.45 439.73,2079.45 459.73,2059.45 459.73,2005.95 C64.1@519.73,1945.95 R92.2@584.73,1945.95
NetC3_1: C3.1 R5.1 R8.2 R14.1 R18.2 U4.1 | length 1198.6
  Top Layer w15: R5.1@462.73,2501.95 665.73,2501.95 R8.2@787.24,2623.45 787.24,2684.45 C3.1@786.24,2685.45 R18.2@690.99,2685.45 ; R14.1@534.73,3022.95 534.73,2764.27 612.79,2686.21 R18.2@688.75,2686.21 680,2694.96 680,2803.22 703.63,2826.85 U4.1@770.6,2826.85
NetC3_2: C3.2 R7.1 R13.2 U4.4 | length 529.8
  Top Layer w15: R13.2@846.61,3101.95 836.73,3092.08 836.73,2769.45 854.13,2752.05 U4.4@878.87,2752.05 878.87,2715.09 C3.2@849.73,2685.95 ; C3.2@849.23,2685.45 C3.2@849.73,2685.95 ; R7.1@914.73,2685.95 C3.2@849.73,2685.95
NetC4_2: C4.2 C5.2 R6.1 R9.2 U1.1 U3.1
NetC10_1: C10.1 R10.2 U3.2 | length 157.2
  Top Layer w15: U3.2@2889.3,4701.58 2968.24,4701.58 C10.1@2974.73,4695.08 2976.23,4696.58 R10.2@3043.24,4696.58
NetC10_2: C10.2 R17.2 U3.3 | length 153.1
  Top Layer w15: U3.3@2889.3,4751.58 C10.2@2968.24,4751.58 ; C10.2@2974.73,4758.07 R17.2@3039.73,4758.07
  Top Layer w20: C10.2@2968.24,4751.58 C10.2@2974.73,4758.07
NetC11_1: C11.1 R12.2 R13.1 | length 133.2
  Top Layer w15: R13.1@848.61,3164.95 850.1,3166.44 C11.1@850.1,3233.45 848.61,3234.95 R12.2@848.61,3296.95
NetC11_2: C11.2 R15.2 R16.1 | length 134.1
  Top Layer w15: R16.1@783.61,3164.95 787.11,3168.45 C11.2@787.11,3233.45 788.61,3234.95 R15.2@788.61,3296.95
NetC12_1: C12.1 R14.2 U2.2 U2.5 | length 680.6
  Top Layer w15: R14.2@534.73,3085.95 534.73,3144.45 C12.1@528.24,3150.95 528.24,3194.68 v1(540.51,3206.95) U2.2@540.51,3290.06 ; v1(640.09,3569.42) 640.09,3505.05 U2.5@640.51,3504.62
  Bottom Layer w15: v1(540.51,3206.95) 640.09,3306.53 v1(640.09,3569.42)
NetC13_1: C13.1 R16.2 R21.2 R22.2 U4.3 | length 393.9
  Top Layer w15: U4.3@770.6,2752.05 793.45,2752.05 812.73,2771.33 812.73,2882.95 R22.2@782.23,2913.45 R21.2@782.23,2975.45 C13.1@782.23,3037.45 783.61,3038.83 R16.2@783.61,3101.95
NetC17_1: C17.1 R26.1 R29.2 R35.1 R39.2 U8.1 | length 1869.7
  Top Layer w15: R26.1@581.73,2248.95 883.16,2550.37 1400.82,2550.37 R29.2@1468.76,2618.32 1468.76,2680.32 R39.2@1352.75,2680.32 ; R35.1@1124.73,3022.95 1124.73,2899.45 1344.83,2679.35 R39.2@1349.68,2679.35 R39.2@1354.33,2674.7 ; R39.2@1348.1,2684.97 1348.1,2799.66 1364.96,2816.52 U8.1@1430.93,2816.52 U8.1@1431.93,2816.52
NetC17_2: C17.2 R28.1 R34.2 U8.4 | length 415.2
  Top Layer w15: R34.2@1507.13,2977.12 R34.2@1516.26,2967.99 1495.43,2947.17 1497.06,2945.54 1497.06,2759.12 1514.47,2741.72 U8.4@1539.2,2741.72 1539.2,2687.76 1531.76,2680.32 1598.52,2680.32 R28.1@1601.04,2682.84
NetC18_2: C18.2 C19.2 R27.1 R30.2 U5.1 U7.1
NetC24_1: C24.1 R31.2 U7.2 | length 157.2
  Top Layer w15: U7.2@2891.65,3176.32 2970.58,3176.32 C24.1@2977.08,3169.83 3044.09,3169.83 R31.2@3045.58,3171.32
NetC24_2: C24.2 R38.2 U7.3 | length 158.1
  Top Layer w15: U7.3@2891.65,3226.32 2970.58,3226.32 C24.2@2977.08,3232.82 3042.08,3232.82 R38.2@3045.58,3236.32
NetC25_1: C25.1 R33.2 R34.1 | length 138.2
  Top Layer w15: R34.1@1579.25,2967.99 1580.74,2966.5 C25.1@1647.75,2966.5 1649.25,2967.99 R33.2@1716.26,2967.99
NetC25_2: C25.2 R36.2 R37.1 | length 138.2
  Top Layer w15: R37.1@1579.25,3027.99 1646.26,3027.99 C25.2@1647.75,3029.49 1649.25,3027.99 R36.2@1716.26,3027.99
NetC26_1: C26.1 R35.2 U6.2 U6.5 | length 647.2
  Top Layer w15: v1@1123.4,3212.19 v1(1124.21,3211.37) ; U6.2@1124.21,3294.47 v1(1124.21,3211.37) ; R35.2@1124.73,3085.95 1124.32,3086.36 C26.1@1124.32,3152.19 1124.32,3211.27 v1(1124.21,3211.37) ; U6.5@1218.8,3514.45 1283.17,3514.45 v1(1284.6,3515.88)
  Bottom Layer w15: v1(1124.21,3211.37) 1284.6,3371.76 v1(1284.6,3515.88)
NetC27_1: C27.1 R37.2 R42.2 R43.2 U8.3 | length 407.6
  Top Layer w15: U8.3@1431.93,2741.72 1457.66,2741.72 1474.06,2758.12 1474.06,2872.62 R43.2@1443.56,2903.12 R42.2@1443.56,2966.12 1444.03,2966.59 C27.1@1444.03,3030.62 1446.66,3027.99 R37.2@1516.26,3027.99
NetC31_1: C31.1 R47.1 R50.2 R56.1 R60.2 U12.1 | length 1540.5
  Top Layer w15: R47.1@581.73,2055.95 908.24,1729.45 1476.99,1729.45 R60.2@1517.45,1769.91 ; R50.2@1455.96,1646.4 C31.1@1520.96,1646.4 ; R56.1@1516.96,1833.41 1517.45,1832.91 R60.2@1517.45,1769.91 ; 1520.96,1666.4 1520.96,1766.4 R60.2@1517.45,1769.91 ; U12.1@1663.36,1688.04 U12.1@1663.36,1689.04 1663.36,1755.01 1648.32,1770.04 1612.91,1770.04 1612.77,1769.91 R60.2@1517.45,1769.91
NetC31_2: C31.2 R49.1 R55.2 U12.4 | length 521.6
  Top Layer w15: R49.1@1522.45,1519.91 1520.96,1521.4 1520.96,1583.41 1523.59,1580.77 U12.4@1588.55,1580.77 1588.55,1607.5 1600.96,1619.91 1937.78,1619.91 R55.2@1943.24,1614.45
NetC32_2: C32.2 C33.2 R48.1 R51.2 U9.1 U11.1
NetC38_1: C38.1 R52.2 U11.2 | length 152.2
  Top Layer w15: U11.2@2889.3,1754.45 2968.24,1754.45 C38.1@2974.73,1747.95 3036.74,1747.95 R52.2@3038.24,1749.45
NetC38_2: C38.2 R59.2 U11.3 | length 152.2
  Top Layer w15: U11.3@2889.3,1804.45 2968.24,1804.45 C38.2@2974.73,1810.95 3036.74,1810.95 R59.2@3038.24,1809.45
NetC39_1: C39.1 R54.2 R55.1 | length 126.1
  Top Layer w15: R55.1@2006.23,1614.45 2007.73,1612.95 C39.1@2069.73,1612.95 R54.2@2131.74,1612.95
NetC39_2: C39.2 R57.2 R58.1 | length 129.1
  Top Layer w15: R58.1@2006.23,1679.45 2009.73,1675.95 C39.2@2069.73,1675.95 2071.23,1674.45 R57.2@2133.24,1674.45
NetC40_1: C40.1 R56.2 U10.2 U10.5 | length 629.8
  Top Layer w15: U10.2@1375.17,1950.91 v1(1429.73,1950.91)
  Top Layer w20: v1@1091.46,2050.91 U10.5@1160.6,2050.91 ; v1(1429.73,1950.91) 1429.73,1922.62 C40.1@1454.96,1897.4 1455.96,1896.4 R56.2@1516.96,1896.4
  Bottom Layer w20: v1(1091.44,2050.88) 1191.41,1950.91 v1(1429.73,1950.91)
NetC41_1: C41.1 R58.2 R63.2 R64.2 U12.3 | length 401.1
  Top Layer w15: U12.3@1588.55,1688.04 1588.55,1662.31 1604.96,1645.91 1718.91,1645.91 R64.2@1752.41,1679.41 R63.2@1814.41,1679.41 C41.1@1876.41,1679.41 R58.2@1943.24,1679.45 R58.2@1943.24,1679.45
NetC43_1: C43.1 C44.1 R67.2 U13.2 | length 230.9
  Top Layer w25: R67.2@3456.84,392.32 3456.84,321.81 C43.1@3462.33,316.32 3456.84,310.82 C44.1@3456.84,240.32 3457.33,239.82 U13.2@3457.33,166.13
NetC46_1: C46.1 R71.1 R76.2 U15.4 | length 321.6
  Top Layer w15: R76.2@383.73,1360.9 381.33,1363.3 U15.4@381.33,1445.27 381.33,1473 396.23,1487.91 C46.1@518.73,1487.91 518.73,1427.91 R71.1@522.23,1424.4
NetC46_2: C46.2 R72.2 R78.1 U15.1 | length 622
  Top Layer w15: R78.1@399.73,1967.95 399.73,1794.45 583.73,1610.45 R72.2@583.73,1550.9 C46.2@518.73,1550.9 516.09,1553.54 U15.1@456.13,1553.54
NetC51_1: C51.1 R74.2 U14.2 | length 157.2
  Top Layer w20: U14.2@2886.3,-268.55 2965.24,-268.55 C51.1@2971.73,-275.05 3038.74,-275.05 R74.2@3040.24,-273.55
NetC52_1: C52.1 R75.2 R76.1 | length 134.1
  Top Layer w15: R75.2@378.73,1165.9 378.73,1227.91 C52.1@380.23,1229.4 380.23,1294.4 R76.1@383.73,1297.91
NetC52_2: C52.2 R80.2 R81.1 | length 133.2
  Top Layer w15: R80.2@318.73,1165.9 318.73,1227.91 C52.2@317.23,1229.4 318.73,1230.9 R81.1@318.73,1297.91
NetC54_1: C54.1 R81.2 R85.2 R86.2 U15.3 | length 261.4
  Top Layer w15: R81.2@318.73,1360.9 318.73,1422.9 C54.1@315.23,1426.4 R85.2@315.23,1489.4 R86.2@315.23,1554.4 316.09,1553.54 U15.3@381.33,1553.54
NetC57_1: C57.1 R87.1 R91.2 U17.4 | length 406.2
  Top Layer w15: 1512.03,1193.81 1524.33,1181.5 ; R91.2@1514.48,1056.75 1512.03,1059.2 1512.03,1169.2 ; U17.4@1558.87,1181.5 1524.33,1181.5 ; R87.1@1576.53,1328.41 1576.03,1327.91 C57.1@1512.03,1327.91 1512.03,1169.2 ; 1512.03,1169.2 1524.33,1181.5
NetC57_2: C57.2 R88.2 R92.1 U17.1 | length 1259.6
  Top Layer w15: 584.73,1860.27 584.73,1744.45 771.18,1558 1281.94,1558 R88.2@1449.04,1390.91 C57.2@1449.04,1327.91 ; U17.1@1450.6,1256.31 C57.2@1450.6,1326.34
NetC62_1: C62.1 R89.2 U16.2 | length 172.2
  Top Layer w15: U16.2@2889.3,229.45 2983.24,229.45 C62.1@2989.73,222.95 2991.23,224.45 R89.2@3058.24,224.45
NetC63_1: C63.1 R90.2 R91.1 | length 136.3
  Top Layer w10: C63.1@1648.28,1055.95 C63.1@1648.77,1055.45
  Top Layer w15: R91.1@1579.77,1054.45 1581.27,1055.95 C63.1@1648.28,1055.95 ; C63.1@1648.77,1055.45 R90.2@1715.28,1055.45
NetC63_2: C63.2 R93.2 R94.1 | length 137.2
  Top Layer w15: R94.1@1579.77,994.45 1581.27,992.95 C63.2@1648.28,992.95 1650.77,995.45 R93.2@1715.28,995.45
NetC65_1: C65.1 R94.2 R98.2 R99.2 U17.3 | length 257.9
  Top Layer w15: U17.3@1450.6,1181.5 1451.23,1180.88 R99.2@1451.23,1120.91 R98.2@1451.23,1055.91 1451.23,1045.91 C65.1@1451.23,990.91 1513.24,990.91 R94.2@1516.78,994.45
NetC71_1: C71.1 R102.2 U20.2 | length 206.3
  Top Layer w20: R102.2@1298.73,2449.72 R102.2@1297.23,2448.23 1360.73,2448.23 C71.1@1364,2451.5 1499.37,2451.5 U20.2@1499.87,2451
NetC92_2: C92.2 C93.2 J11.1 R146.2 | length 274.1
  Top Layer w20: R146.2@134.73,3099.45 C92.2@134.73,3009.45 143.24,3000.95 C93.2@143.24,2929.45 141.73,2927.95 J11.1@141.73,2829.45
NetC94_1: C94.1 C95.1 J11.2 R144.1 | length 265
  Top Layer w20: J11.2@241.73,2829.45 C95.1@338.24,2829.45 338.24,2903.95 C94.1@341.73,2907.45 R144.1@341.73,2996.45
NetC103_1: C103.1 R155.2 R158.1 U25.2 | length 225.2
  Bottom Layer w15: R155.2@715.25,1244.45 R158.1@715.25,1306.45 C103.1@715.25,1369.45 747.76,1369.45 776.76,1340.45 U25.2@803.47,1340.45
NetC107_1: C107.1 R160.2 R161.2 R162.2 U25.3 U25.6 | length 573.2
  Bottom Layer w15: C107.1@715.25,1433.45 758.25,1390.45 U25.3@803.47,1390.45 876.76,1390.45 901.76,1415.45 ; R162.2@839.76,1508.95 R161.2@901.76,1508.95 ; R160.2@977.76,1507.95 902.76,1507.95 R161.2@901.76,1508.95 ; U25.6@1018.04,1390.45 926.76,1390.45 901.76,1415.45 ; 901.76,1415.45 R161.2@901.76,1508.95
NetC113_1: C113.1 R165.2 R166.1 R167.1 U25.5 | length 377.7
  Top Layer w15: v1(1094,1509) 1095.73,1507.27 R167.1@1095.73,1398.22
  Bottom Layer w15: U25.5@1018.04,1440.45 1050.76,1440.45 1067.3,1456.99 C113.1@1098.24,1456.99 ; v1(1094,1509) 1098.24,1504.76 C113.1@1098.24,1456.99 ; R165.2@1097.24,1331.99 1097.24,1392.99 R166.1@1098.24,1393.99 C113.1@1098.24,1456.99
NetD1_2: D1.2 D2.1 | length 130
  Bottom Layer w30: D2.1@4488.75,119.45 D1.2@4618.73,119.45
NetD2_2: D2.2 R66.1 R68.2 | length 364.1
  Bottom Layer w30: D2.2@4314.73,119.45 4314.73,34.36 R66.1@4424.65,-75.55 4424.65,-176.37 R68.2@4440.73,-192.46
NetD3_1: D3.1 R100.2 | length 257.6
  Bottom Layer w40: R100.2@2952.73,4237.45 3198.99,4237.45 D3.1@3206.99,4229.45
NetD4_1: D4.1 R101.2 | length 257.8
  Bottom Layer w40: R101.2@2951.86,1324.86 3200.58,1324.86 D4.1@3206.99,1318.45
NetD5_1: D5.1 R108.1 U18.15 | length 285.4
  Top Layer w20: U18.15@2870.93,3923 2974,3923 3010,3959 D5.1@3010,3975.59 3010,3989.37 3045.43,4024.8 3091.26,4024.8 R108.1@3094.9,4028.45
NetD5_2: D5.2 R104.1 | length 96.8
  Top Layer w20: D5.2@3010,3900.79 3035.79,3900.79 3060.45,3925.45 R104.1@3094.65,3925.45 R104.1@3093.3,3926.8
NetD6_1: D6.1 R109.1 U19.15 | length 280.5
  Top Layer w20: U19.15@2867.86,1012 2969.26,1012 3010,1052.74 D6.1@3010,1070.59 3046.76,1070.59 R109.1@3094.03,1117.86
NetD6_2: D6.2 R105.1 | length 91.7
  Top Layer w20: D6.2@3010,995.79 3035.79,995.79 3054.86,1014.86 R105.1@3093.77,1014.86
NetD7_1: D7.1 R118.1 U18.10 | length 253.7
  Top Layer w20: U18.10@2870.93,3673 2919,3673 2967.59,3624.41 D7.1@3005,3624.41 3049.96,3579.45 R118.1@3085.9,3579.45
NetD7_2: D7.2 R114.1 | length 87
  Top Layer w20: D7.2@3005,3699.21 3071.14,3699.21 R114.1@3085.9,3684.45
NetD8_1: D8.1 R119.1 U19.10 | length 275.7
  Top Layer w20: U19.10@2867.86,762 2975,762 3000,737 D8.1@3000,724.41 3000,703 3034.14,668.86 R119.1@3085.03,668.86
NetD8_2: D8.2 R115.1 | length 95.5
  Top Layer w20: D8.2@3000,799.21 3025.79,799.21 3051.14,773.86 R115.1@3085.03,773.86
NetD9_1: D9.1 R120.2 | length 289.2
  Bottom Layer w40: R120.2@2951.73,2800.45 3124.99,2800.45 D9.1@3206.99,2718.45
NetD10_1: D10.1 R126.1 U22.15 | length 284.7
  Top Layer w20: U22.15@2860,2494.45 2935.73,2494.45 2983.39,2542.1 3047.39,2542.1 3093.9,2588.62 R126.1@3093.9,2600.45
NetD10_2: D10.2 R122.1 | length 100.2
  Top Layer w20: D10.2@3006.23,2471.24 3031.24,2471.24 3057.45,2497.45 R122.1@3093.65,2497.45 R122.1@3092.3,2498.8
NetD11_1: D11.1 R132.1 U22.10 | length 257.3
  Top Layer w20: U22.10@2866.86,2244 2965.41,2244 D11.1@3000,2209.41 3056.31,2153.1 3056.31,2151.45 R132.1@3084.9,2151.45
